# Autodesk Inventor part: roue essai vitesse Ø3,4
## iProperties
Created: 2011-11
Part Number: roue essai vitesse Ø3,4
Document SubType Name: Modeling
Designer: Laur
Density: 1 g/cm^3
Author: Laur
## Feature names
1. Extrusion1
2. Extrusion2
3. Extrusion3
